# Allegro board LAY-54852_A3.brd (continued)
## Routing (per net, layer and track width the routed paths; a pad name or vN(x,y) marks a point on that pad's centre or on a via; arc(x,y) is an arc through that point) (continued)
GND_CHASSIS:
  vias: v1(78.14,8.1) v1(78.15,6) v1(78.44,1.46) v1(79.18,2.83) v1(80.35,1.39) v1(81.82,2.79) v1(83.01,1.44) v1(83.96,2.81) v1(84.07,12.31) v1(84.42,8.27) v1(84.43,6.17) v1(85.65,1.39) v1(85.84,12.38) v1(86.07,6.39) v1(86.08,4.3) v1(86.05,2.82) v1(86.61,10.86) v1(86.64,9.58) v1(87.42,12.33) v1(87.78,1.41) v1(87.83,5.11) v1(87.82,2.88) v1(88.38,10.93) v1(88.41,9.64) v1(88.85,12.37) v1(89.4,2.83) v1(89.53,8.55) v1(89.54,6.45) v1(89.88,1.42) v1(89.96,10.88) v1(89.99,9.59) v1(90.61,12.43) v1(91.6,1.38) v1(92.04,2.79) v1(92.2,12.38) v1(93.49,1.45) v1(94.18,2.81) v1(95.09,8.4) v1(95.06,6.62) v1(95.07,4.52) v1(95.83,1.57) v1(96.27,2.82) v1(97.18,8.41) v1(97.21,6.53) v1(97.22,4.44) v1(97.43,1.52)
VBUS1_DET_3V3: length 91.9
  TOP w0.081: U101.B3 85.25,56.45 85.25,56.98
  TOP w0.091: R301.1 22.87,29.43 22.06,30.24 22.06,36.23 23.34,37.51 27.24,37.51 29.46,39.73 32.2,39.73 32.77,40.31 32.77,44.52 34.72,46.47 45.94,46.47 45.96,46.45 v1(46.79,46.45) ; 85.25,56.98 85.25,57.34 84.83,57.76 84.83,60.33 84.46,60.7 82.98,60.7 82.25,61.43 69.75,61.43 65.64,57.31 56.67,57.31 55.44,56.08 55.44,51.03 54.06,49.65 51.51,49.65 47.7,45.84 v1(47.56,45.84)
  BOTTOM w0.091: v1(46.79,46.45) 46.98,46.25 47.15,46.25 v1(47.56,45.84)
VBUS_DBG: length 13.9
  TOP w0.381: J1708.A9 16.56,5.99 J1708.B4 ; J1708.B9 14.06,5.99 J1708.A4 14.06,7.84 TVS1401.2
  TOP w0.508: TVS1401.2 12.06,9.85 11.62,9.85 L1702.1
  BOTTOM w0.381: J1708.B9 14.11,7.65 14.81,8.35 16.04,8.35 16.51,7.87 J1708.B4
VBUS_IN:
  vias: v1(21.68,20.13) v1(21.68,19.52) v1(22.42,20.11) v1(22.43,19.47) v1(41.59,22.14) v1(41.6,21.53) v1(42.33,22.12) v1(42.35,21.48)
VBUS_OVLO_TH: length 3
  TOP w0.091: U302.B3 49.42,23.23 R304.2 49.71,23.51 R1759.1
VBUS_USB_DBG: length 7.4
  TOP w0.381: C1409.1 9.16,12.08 8.89,12.34 U1410.1 ; C1409.1 9.66,10.81 L1702.2 ; C1409.1 9.66,12.08 C1725.1 9.66,14.54 C1726.1 9.04,14.55 8.73,14.24 U1410.3
VCC_3V6: length 2.6
  TOP w0.305: U901.9 37.82,35.32 37.43,35.72 C907.1 36.69,36.56 R908.1
VCC_FT_1V8: length 38.9
  TOP w0.203: C1723.1 3.45,23.9 3.57,24.02 4.07,24.02 4.22,23.87 U1706.64
  TOP w0.254: v1(12.92,23.03) 13,22.95 U1706.12 ; v1(13.58,32.18) 13.53,32.18 13,32.71 U1706.37
  TOP w0.508: L1404.1 4.73,34.8 8.37,31.16 13.28,31.16 13.58,31.46 v1(13.58,32.18) ; v1(12.92,23.03) 12.15,23.8 7.39,23.8 6.74,23.16 C1723.1
  BOTTOM w0.508: C1724.1 v1(12.92,23.03) 12.92,24.05 13.58,24.71 v1(13.58,32.18) C1408.1
VCC_FT_3V3: length 247.7
  TOP w0.254: U1706.20 18.54,25.37 C1420.1 ; U1706.31 18.65,30.87 C1423.1 ; v1(4.36,30.73) 4.5,30.87 U1706.50 ; U1404.3 27.72,62.43 C1424.1 ; U1706.56 v1(4.27,27.87) ; v1(10.65,32.16) 10.5,32.31 U1706.42 ; U1713.2 11.77,48.51 12.95,47.33 C1720.1 ; U1409.21 20.96,53.72 C1461.1
  TOP w0.305: R1816.1 v1(10.38,58.21) ; R1815.1 v1(8.04,69.15)
  TOP w0.381: R1421.2 v1(9.74,39.66) ; R1452.1 v1(19.64,22.52) ; v1(20.12,29.66) 19.84,29.38 R1727.2 ; v1(135,45.74) R1053.1 135.08,45.06 R1056.1 ; v1(2.27,38.85) 2.62,39.2 R1735.1 ; R1453.1 5.51,58.72 v1(5.8,58.42) ; R1467.1 v1(7.09,65.4) ; R1730.2 7.51,39.02 v1(7.51,38.65) ; R1736.1 3.82,38.93 v1(3.9,38.85) ; U1406.8 14.56,60.79 C1432.1 v1(14.55,59.76) ; C1420.1 v1(18.58,25.95) ; R1468.1 5.59,61.48 v1(5.89,61.18) ; v1(18.4,53.59) 18.7,53.29 C1460.1 19.3,53.27 C1461.1 ; v1(12.71,65.05) 12.53,64.86 R1450.1 ; U1408.1 20.49,38.34 C1435.1 19.85,36.74 C1434.1 v1(19.98,35.98) ; C1720.1 13.51,47.3 C1719.1 v1(12.89,46.4) ; R1486.1 22.67,51.67 21.56,50.56 v1(18.61,50.56) ; D1703.C v1(15.29,15.91) ; C1423.1 18.68,31.13 v1(18.29,31.51) ; U1405.6 v1(4.67,40.81) ; v1(11.91,67.57) 11.88,67.54 C1433.1 12.38,66.82 12.53,66.97 U1407.6 ; R1485.1 16.3,54.8 v1(16.53,54.57) ; R1465.1 6.41,55.83 v1(6.46,55.78) ; C1424.1 27.27,61.98 C1425.1 27.27,60.35 26.92,60 25.75,60 25.32,60.43 25.32,64.14 R1451.1 24.54,65.34 24.2,65.68 23.32,65.68 22.57,66.42 20.25,66.42 17.57,63.74 v1(14.59,63.74) ; R1734.1 5.92,47.56 v1(5.71,47.77) ; R1742.1 v1(15.72,65.66) ; R1729.2 v1(13.16,40.12) ; L1703.1 v1(13.57,16.06) ; L1704.1 v1(8.23,16.12) ; v1(4.91,51.39) 5.15,51.63 R1733.2 ; R1748.1 v1(7.21,68.93) ; R1737.1 v1(16.55,18.14) ; R1726.2 v1(20.12,28.3)
  TOP w0.508: v1(2.61,14.6) 2.64,14.63 D1704.C
  BOTTOM w0.254: C1418.1 v1(4.36,30.73)
  BOTTOM w0.381: v1(4.27,27.87) 4.27,27.87 C1417.1 ; C1429.1 4.67,41.03 v1(4.67,40.81) ; v1(135,45.74) 133.81,46.93 133.81,69.57 133.92,69.68 133.92,77.39 126.42,84.89 14.94,84.89 13,82.95 13,81.09 13.19,80.9 13.19,69.8 11.91,68.51 v1(11.91,67.57) ; C1419.1 10.48,32.34 v1(10.65,32.16)
VDD_1V8: length 213.4
  TOP w0.127: v1(60.51,26.65) 61.07,26.65 61.66,27.25 U701.14
  TOP w0.203: v1(105.21,42.96) 105.21,43.02 104.98,43.24 U501.C6 ; U501.N4 U501.M4 ; U501.N4 U501.P3 103.29,37.71 v1(103.29,37.32) ; U501.N4 U501.P5 104.36,37.78 104.36,37.25 v1(104.36,37.25) ; v1(88.49,51.21) U101.L9 U101.L11 ; U101.L6 86.99,52.16 v1(86.95,52.2)
  TOP w0.254: C1436.1 20.84,40.11 21.26,39.69 U1408.11 ; R1779.1 96.13,30.73 v1(95.84,30.44) ; U201.T9 68.28,49.13 67.99,48.84 v1(67.96,48.84) ; C923.1 119.8,28.32 U906.1 ; v1(74.71,56.08) 74.71,55.68 U201.F1 ; v1(74.46,48.81) 74.46,48.87 U201.G9 ; v1(60.87,56.47) 61.14,56.74 66.57,56.74 v1(67.3,56.01) 67.63,55.68 U201.U1 ; U201.T4 68.28,53.28 v1(67.95,53.61) ; U201.G4 74.44,53.51 v1(74.44,53.62) ; U904.11 130.37,23.94 C1756.1
  TOP w0.305: v1(116.05,28.41) 116.05,23.26 115.04,22.26 115.04,20.91 R956.2
  TOP w0.381: v1(74.57,43.44) 79.55,43.44 80.06,42.94 80.06,39.41 77.38,36.73 77.38,34.74 v1(77.42,34.7) ; R952.1 v1(131.59,3.75) R951.1 ; v1(27.62,41.37) 27.27,41.03 R1460.1 26.89,40.86 26.16,40.12 v1(23.86,40.12) ; v1(15.28,79.12) 15.2,79.04 L1301.1 ; v1(61.02,58.83) 63.63,58.83 68,63.2 R1767.1 ; R502.1 97.51,39.12 v1(97.84,38.79) ; R501.1 v1(99.09,42.84) ; Q1406.2 28.58,54.01 R1756.1 v1(27.43,53.19) ; C1756.1 130.12,23.24 v1(129.68,23.24) ; C1437.1 19.85,39.98 C1436.1 19.98,41.47 D1407.A 21.78,43.27 23.79,43.27 v1(23.87,43.19) ; v1(97.34,67.77) 97.66,67.45 C802.1 99.67,67.37 U802.5 ; R510.1 v1(79.89,33.6) ; R1441.1 v1(47.87,66.67) ; R65.2 72.69,20.84 72.26,20.41 v1(72.17,20.41) 72.1,20.41 71.72,20.79 R64.2 ; v1(119.56,27.26) 119.3,27.53 C923.1 ; J1405.1 v1(49.71,69.7) ; v1(94.56,70.99) 92.88,70.99 92.41,71.46 90.25,71.46 89.67,72.05 v1(87.04,72.05) ; C1448.1 31.84,40.9 R1459.1 29.58,40.9 27.91,39.23 v1(27.62,39.23) ; v1(98.53,26.73) L1201.1 v1(99.19,26.01) ; v1(126.9,22.84) 126.9,20.87 127.36,20.41 v1(127.36,18.7)
  L2_GND w0.254: v1(88.49,51.21) 87.53,52.17 87.13,52.17 87.09,52.2 v1(86.95,52.2)
  L3_PWR w0.203: v1(74.44,53.62) 74.9,53.15 74.9,49.25 v1(74.46,48.81)
  BOTTOM w0.203: v1(60.51,26.65) 60.76,26.4 60.76,20.76 v1(59.43,19.43)
  BOTTOM w0.254: C201.1 67.28,56.03 v1(67.3,56.01) 68.53,54.78 C202.1 68.06,53.71 v1(67.95,53.61) ; v1(105.21,42.96) 105.14,43.03 C506.1 ; C504.1 104.36,36.51 v1(104.36,37.25) 104.37,37.25 C507.1 ; v1(88.49,51.21) 88.73,51.44 C116.1 ; v1(86.95,52.2) 86.98,52.17 C115.1 ; C505.1 103.14,37.47 v1(103.29,37.32) ; v1(74.71,56.08) 74.95,55.84 C203.1 74.95,54.91 74.44,54.39 v1(74.44,53.62) ; v1(67.96,48.84) 67.93,48.81 C209.1 67.93,47.03 v1(67.3,46.4) 67.37,46.34 C205.1
  BOTTOM w0.381: v1(94.56,70.99) 94.56,70.55 v1(97.34,67.77) ; v1(27.62,39.23) v1(27.62,41.37) 27.43,41.56 v1(27.43,53.19) 28.54,54.31 31.09,54.31 43.45,66.67 v1(47.87,66.67) ; v1(119.56,27.26) 119.47,27.36 C922.1 ; v1(92.15,76.92) 88.94,76.92 87.54,78.32 86.68,78.32 86.19,77.83 86.19,77.19 87.04,76.35 v1(87.04,72.05) ; v1(95.84,30.44) 95.84,32.66 99.39,36.2 ; v1(23.87,43.19) 24.18,42.88 24.18,40.45 v1(23.86,40.12)
  BOTTOM w0.508: v1(77.42,34.7) 77.47,34.65 78.84,34.65 v1(79.89,33.6)
  vias: v1(58.69,22.85) v1(58.7,22.27) v1(58.71,21.7) v1(59.16,73.59) v1(59.24,22.86) v1(59.26,22.27) v1(59.27,21.69) v1(59.56,73.19) v1(59.95,72.82) v1(60.78,47.25) v1(60.88,55.61) v1(60.85,46.35) v1(73.57,45.61) v1(74.62,46.35) v1(117.71,29.76) v1(117.84,28.54) v1(126.35,22.83) v1(126.59,23.28)
VDD_3V3: length 195.2
  TOP w0.127: U701.21 64.91,26.35
  TOP w0.203: U1709.G3 104.52,29.93 v1(104.7,30.11) ; U1709.A3 104.52,25.8 v1(104.49,25.77) ; U301.3 v1(68.24,15.3) ; U501.E6 v1(104.98,42.02) ; 65.52,26 65.38,26.14 65.38,26.51 65.31,26.58 U701.22 ; U101.H13 v1(90.49,52.73) U101.K13 ; U501.F5 104.21,41.9 104.17,41.94 v1(104.1,41.94) ; v1(65.63,22.46) 65.37,22.46 65.08,22.76 65.08,25.82 64.91,25.99 64.91,26.35 ; v1(88.47,54.71) U101.E8 ; U501.J10 107.22,40.4 v1(107.35,40.26) ; U501.K9 v1(106.48,39.45)
  TOP w0.254: C921.1 120.07,29.63 U906.11 ; U1713.3 12.23,48.91 12.48,49.16 C1722.1 ; C805.1 113.63,70.81 U805.14 ; C804.1 131.47,69.14 131.02,69.6 U803.14 ; C1401.1 122.52,69.22 121.71,68.41 U1401.8 ; C1703.1 25.17,74.27 U1702.14 ; C1755.1 130.51,25.29 U904.1 ; U1401.5 123.55,66.73 C1403.1 ; v1(37.36,15.25) 37.72,15.61 U401.3 ; R613.1 6.9,71.21 TP608.1 ; v1(106.21,62.42) 106.31,62.32 U801.27 ; C1426.1 27.6,62.83 U1404.2 ; R1502.1 v1(30.97,67.87) ; U804.14 v1(102.92,71.33)
  TOP w0.381: C1755.1 130.69,27.61 ; 130.69,27.61 v1(130.22,28.07) ; 130.69,27.61 133.4,27.61 R1813.1 ; v1(25.1,28.68) 24.78,29 R1768.1 ; v1(101.66,68.29) 101.36,68.29 101.33,68.33 R808.1 ; v1(117.82,61.37) 117.54,61.09 R817.1 ; C1703.1 C1704.1 v1(26.07,73.71) ; v1(27.83,64.15) 27.77,64.09 C1427.1 27.3,63.52 27.4,63.42 C1426.1 ; R1765.1 v1(66.58,9.72) ; D1703.A v1(18.78,16.66) ; R1420.1 v1(123.12,62.68) ; v1(85.15,38.34) 85.15,37.81 L501.1 84.27,37.8 v1(84.27,38.31) ; D1501.A 23.07,76.74 v1(23.09,76.73) ; v1(116.24,71.27) 116.42,71.09 R1402.1 R1404.1 ; C1201.1 104.75,30.6 104.7,30.55 v1(104.7,30.11) ; v1(123.56,70.14) C1401.1 123.58,69.2 C1404.1 123.62,67.78 C1403.1 v1(123.62,66.04) ; D1502.A 33.97,75.42 v1(34.11,75.28) ; U801.31 106.44,60.32 v1(106.34,60.22) ; R1403.1 116.12,65.3 v1(115.92,65.51) ; R309.1 v1(102.46,63.93) ; R705.1 v1(71.96,23.63) ; v1(95.15,25.07) 94.67,25.55 L502.1 95.4,27.25 95.4,28.35 95.05,28.7 R506.1 ; v1(12.76,48.2) C1721.1 C1722.1 ; R1407.1 94.55,73.43 v1(94.34,73.64) ; R804.1 v1(103.56,64.35) ; v1(13.06,52.45) 13.3,52.2 R1718.2 ; v1(113.81,72.58) C806.1 113.79,71.92 C805.1 ; R802.1 R801.1 v1(103.48,60.14) ; R306.1 R308.1 102.46,59.52 v1(102.41,59.57) ; J1406.2 61.98,73.53 C1412.1 v1(62.88,73.25) ; U1308.5 17.36,72.22 C1324.1 17.32,72.69 v1(17.15,72.86) ; R1221.1 113.79,35.67 113.79,35.73 v1(113.89,35.83) ; R1203.1 99.54,17.08 R1202.1 v1(100.25,16.32) ; v1(8.43,70.8) 8.01,71.21 TP608.1 ; R1762.1 v1(51.75,20.96) ; R604.1 v1(46.89,51.53) R603.1 v1(46.89,52.93) R602.1 v1(46.89,54.21) R601.1 ; v1(37.85,21.94) R431.1 36.99,21.41 R1775.1 ; R935.1 118.55,29.39 119.28,30.12 C921.1 119.64,30.78 v1(120.48,30.78) ; R1054.1 130.58,40.01 v1(130.43,39.86) ; R1827.1 v1(74.21,72.68) ; R923.1 v1(126.89,5.25) ; v1(127.82,31.92) 127.88,31.86 R950.1 ; R1333.1 v1(8.97,77.6) ; R505.1 v1(82.81,37.87) ; R913.2 v1(50.25,35.4) ; C804.1 C807.1 130.45,68.97 v1(130.13,69.3) ; v1(102.55,61.65) 102.46,61.73 R307.1 ; R1405.1 v1(122.48,73.69) ; U1307.5 16.83,77.05 C1325.1 16.79,77.53 v1(16.95,77.69) ; R1440.1 v1(47.87,68.92) ; R1406.1 v1(119.02,73.64) ; R213.1 v1(53.84,42.35) ; R1408.1 v1(92.04,73.64)
  TOP w0.762: J1406.1 J1406.2
  BOTTOM w0.203: C155.1 88.5,54.73 v1(88.47,54.71)
  BOTTOM w0.254: v1(90.56,61.26) 90.48,61.18 90.48,58.35 88.98,56.86 C155.1 ; U905.1 120.47,29.64 119.92,30.18 C920.1 ; C411.1 37.39,15.28 v1(37.36,15.25) ; C501.1 107.45,40.16 v1(107.35,40.26) ; U915.A1 116.37,77.71 C956.1 116.37,79.29 C955.1 ; C502.1 105,42 v1(104.98,42.02) ; v1(106.48,39.45) 106.51,39.42 C503.1 ; C119.1 92.03,52.75 C118.1 91.8,53.43 91.6,53.24 90.73,53.24 90.49,53 v1(90.49,52.73)
  BOTTOM w0.305: U908.11 114.43,24.98 C22.1 114.07,26.27 C1792.1 113.93,27.01 v1(113.69,27.25) ; R863.1 118.15,78.6 117.4,79.36 C955.1
  BOTTOM w0.381: v1(65.63,22.46) 66.79,23.63 v1(71.96,23.63) ; v1(120.48,30.78) 119.75,30.78 119.37,30.4 C920.1 ; v1(9.75,70.38) 8.92,69.55 8.92,66.19 10.49,64.62 10.49,60.43 13.06,57.86 v1(13.06,52.45) 13.06,48.5 v1(12.76,48.2) ; U1714.3 99.18,79.66 C1789.1 99.68,78.9 100.67,77.91 100.68,77.91 104.14,74.45 v1(104.51,74.45) ; R1080.1 46.85,52.98 v1(46.89,52.93) ; C955.1 116.44,80.04 116.71,80.31 119.24,80.31 120.82,78.72 v1(120.82,73.99) ; v1(68.24,15.3) 68.34,15.2 C307.1 ; v1(33.68,49.17) 34.08,48.77 R1081.1 35.48,48.8 R1076.1 R1075.1 ; v1(102.92,71.33) 103.2,71.62 C809.1 C808.1 ; C1231.1 103.72,26.66 C1202.1 103.93,26.33 v1(104.49,25.77) ; C801.1 106.34,62.29 v1(106.21,62.42)
  vias: v1(11.96,79.29) v1(12.47,79.27) v1(65.6,18.81) v1(65.6,19.38) v1(66.18,19.38) v1(66.18,18.85) v1(96.07,62.26)
VDD_5V: length 159.4
  TOP w0.254: U401.12 37.32,19.35 36.73,19.94 36.54,19.94 C413.2 ; v1(78.73,79.36) 79.05,79.36 D1402.2 79.15,80.22 v1(78.73,80.22) ; v1(40.4,75.27) 40.4,75.66 R1503.2 41.11,75.67 41.11,75.31 v1(41.03,75.23) ; U301.12 68.64,11.2 69.13,10.72 C309.2
  TOP w0.381: v1(69.59,11.36) 69.59,10.74 C309.2 ; v1(30.13,78.46) 30.43,78.16 R1501.2 ; TP904.1 53.83,37.25 53.41,37.67 52.2,37.67
  TOP w0.508: v1(111.89,18.34) 112.22,18.67 112.22,21.18 v1(112.42,21.39) ; C413.2 35.72,20.23 v1(35.72,19.93)
  TOP w0.635: U1202.3 113.14,30.12 v1(113.02,30.24)
  BOTTOM w0.508: C1219.1 113.29,28.97 111.55,27.23 111.55,22.26 v1(112.42,21.39) ; v1(35.72,19.93) 37.12,21.34 40.17,21.34 50.15,11.36 v1(69.59,11.36) 70.07,10.89 70.07,10.21 70.57,9.7 72.54,9.7 76.79,13.95 106.61,13.95 111,18.34 v1(111.89,18.34)
  BOTTOM w0.635: v1(113.02,30.24) 113.29,29.97 C1219.1
  BOTTOM w0.762: 25.01,35.37 25.01,36.91 25.99,37.9 25.99,55.81 25.16,56.64 25.16,58.55 26.91,60.29 26.91,74.27 30.94,78.3 30.96,78.3
  vias: v1(23.88,35.02) v1(24.39,35.03) v1(24.42,34.52) v1(32.48,79.26) v1(32.98,79.24) v1(33.49,79.22) v1(47.56,35.13) v1(47.56,34.57) v1(47.57,33.91) v1(48.04,34.23) v1(48.04,33.56)
VDD_ANA_0V8: length 7.1
  TOP w0.203: U101.F13 v1(90.49,53.73) ; U101.C4 v1(85.5,55.71) ; U101.M13 v1(90.49,51.69)
  TOP w0.381: v1(58.56,35.88) TP712.1 v1(58.54,36.71)
  L3_PWR w0.305: 90.72,53.33 90.49,53.55 v1(90.49,53.73)
  BOTTOM w0.203: C130.1 90.76,54.22 90.49,53.95 v1(90.49,53.73) ; v1(90.49,51.69) 90.49,52.15 C131.1
  BOTTOM w0.254: C132.1 v1(93.41,48.47) ; v1(85.5,55.71) 85.48,55.72 C133.1
  BOTTOM w0.381: v1(58.56,35.88) 59.15,35.29 R871.2
VDD_ANA_1V8: length 18.4
  TOP w0.203: v1(87.53,54.71) U101.E6 ; U101.F12 v1(89.52,54.21) ; U101.L12 v1(89.99,52.19)
  TOP w0.254: U101.N8 v1(87.49,50.71)
  TOP w0.508: v1(56.11,19.36) 55.9,19.57 L102.2 55.9,21.3 55.76,21.44
  TOP w0.635: 55.76,21.44 55.44,21.44 54.81,22.07 54.81,24.94 53.92,25.84 53.92,27.33 v1(54.47,27.89)
  L2_GND w0.254: v1(89.99,52.19) 89.9,52.19 88.99,51.28 88.99,51 88.7,50.71 v1(87.49,50.71)
  L3_PWR w0.152: 89.99,52.71 89.5,53.21 89.5,53.68
  L3_PWR w0.203: 89.99,52.71 v1(89.99,52.19)
  BOTTOM w0.203: C144.1 87.74,54.91 v1(87.53,54.71) ; C145.1 89.58,54.15 v1(89.52,54.21) ; C146.1 90.03,52.15 v1(89.99,52.19)
VDD_COIN_3V: length 9.8
  BOTTOM w0.381: R1082.1 37.03,58.17 38.44,59.58 39.14,59.58 39.68,59.04 39.68,58.37 40.07,57.98 BT1001.1 40.83,56.9 40.06,56.13 R1072.2
VDD_SNVS_0V8: length 1.6
  TOP w0.203: v1(89.49,55.71) U101.C10
  BOTTOM w0.254: v1(89.49,55.71) 89.49,56.23 89.49,56.24 89.49,56.76 C102.1
VDD_SOC_0V85: length 36.9
  TOP w0.203: v1(73.68,35.7) 73.06,35.08 R711.2 ; U101.K11 v1(89.49,52.71) U101.H11 ; U101.K7 v1(87.49,52.71) U101.H7
  TOP w0.254: TP703.1 73.21,34.47 R701.1
  L3_PWR w0.203: 90.11,49.53 90.55,49.09 90.55,41.72 84.27,35.44 73.93,35.44 v1(73.68,35.7)
  BOTTOM w0.203: v1(87.49,52.71) 87.46,52.74 C111.1 ; C104.1 88.86,52.83 v1(88.99,52.71) ; C107.1 89.48,52.72 v1(89.49,52.71) 89.51,52.68 C106.1
  BOTTOM w0.254: v1(87.49,52.71) 87.51,52.69 C110.1 ; v1(87.99,52.71) 87.99,52.27 C108.1 ; C109.1 86.51,42.59 C105.1 v1(86.98,42.58)
  vias: v1(75,36.72) v1(75.01,36.15) v1(75.69,36.7) v1(75.71,36.19) v1(76.42,36.64) v1(76.41,36.13)
VINT: length 1.8
  TOP w0.203: U701.4 60.92,31.95 v1(60.89,31.99)
  BOTTOM w0.381: C706.1 61.48,31.37 60.89,31.97 v1(60.89,31.99)
ADC_IN0: length 40.8
  TOP w0.081: 87.78,56.92 87.74,56.89 87.74,56.46 U101.B8
  TOP w0.091: 87.78,56.92 87.78,64.41 86.63,65.55 67.12,65.55 65.75,64.18 v1(65.75,63.94) ; v1(62.36,65.19) 61.82,65.73 TP408.1 61.79,67.91 C1413.1 60.68,67.9 R1442.2
  BOTTOM w0.091: v1(65.75,63.94) 64.49,65.19 v1(62.36,65.19)
ADC_IN1: length 39.1
  TOP w0.081: U101.A8 87.99,58.37
  TOP w0.091: R1444.2 60.75,64.54 C1414.1 60.79,64.49 TP409.1 61.97,64.81 v1(61.77,65.01) ; 87.99,58.37 87.99,64.5 86.72,65.77 67.03,65.77 65.18,63.92 65.18,63.79 v1(65.27,63.69)
  BOTTOM w0.091: v1(61.77,65.01) 62.2,64.58 64.39,64.58 v1(65.27,63.69)
ADCDAT1: length 2.7
  TOP w0.081: 106.05,28.07 105.27,28.07 U1709.D2
  TOP w0.102: 106.05,28.07 106.91,28.07 R1208.2
AUD_5V: length 8.4
  TOP w0.508: U1202.5 v1(111.24,30.89)
  TOP w0.635: v1(111.24,30.89) U1202.1
  BOTTOM w0.635: L1205.1 108.75,26.76 110.44,28.46 110.44,30.09 v1(111.24,30.89)
AUD_NINT: length 32.8
  TOP w0.091: R845.2 115.48,58.91 115.48,57.62 113.21,55.35 108.23,55.35 v1(108.14,55.44) ; R1221.2 112.67,35.34 R1204.1 112.67,37.36 113.2,37.88 v1(113.38,37.88)
  BOTTOM w0.091: v1(108.14,55.44) 108.14,55.34 108.17,55.31 108.17,52.01 112.9,47.28 112.9,38.37 v1(113.38,37.88)
AUD_PWREN: length 42.5
  TOP w0.091: R1219.1 112.23,34.73 112.23,37.32 v1(114.05,39.14) ; R831.2 111.82,68.43 108.95,68.43 108.76,68.24 v1(108.75,68.24)
  BOTTOM w0.091: v1(114.05,39.14) 114.08,39.17 114.08,41.05 113.85,41.28 113.85,47.72 111.12,50.46 111.12,53.2 110.8,53.52 110.8,56.19 111.32,56.71 111.32,65.3 108.67,67.95 108.67,68.15 v1(108.75,68.24)
AUD_SCL: length 4
  TOP w0.081: U1709.F1 106.44,28.82
  TOP w0.102: 106.44,28.82 106.55,28.93 106.55,30.66 R1212.2
AUD_SDA: length 3.9
  TOP w0.081: U1709.E2 105.27,28.58 105.76,28.58
  TOP w0.102: R1211.2 106.77,29.89 106.77,28.89 106.45,28.58 105.76,28.58
BCLK1: length 2.6
  TOP w0.081: 106.2,28.32 U1709.E1
  TOP w0.102: R1206.2 106.99,29.14 106.99,28.79 106.53,28.32 106.2,28.32
BT_MODE0: length 2.3
  TOP w0.091: R1731.2 29.5,59.99 U1404.6
BT_MODE1: length 2.1
  TOP w0.091: U1404.7 29.9,59.47 R1732.2
BT_MODE2: length 2.2
  TOP w0.091: R1418.2 30.3,59.77 U1404.8
BT_MODE3: length 3.5
  TOP w0.091: R1419.2 30.95,60.18 30.95,61.82 30.74,62.03 U1404.9
BUF_POR: length 4.3
  TOP w0.091: 101,66.44 101.06,66.51 R811.1 ; 101,66.44 U802.4 ; 101,66.44 R808.2
BYPASS1: length 2.3
  TOP w0.091: U401.4 38.12,15.37 C1737.2
CAN1_RX: length 13.5
  TOP w0.091: v1(22.2,73.03) 22.2,77.91 22.65,78.37 26.75,78.37 R1509.1 ; U1702.4 23.62,71.2 v1(23.56,71.14)
  BOTTOM w0.091: v1(22.2,73.03) 23.56,71.66 v1(23.56,71.14)
CAN1_TX: length 18.5
  TOP w0.091: U1702.1 22.12,72.4 21.82,72.7 21.82,77.85 22.56,78.59 27.58,78.59 28.03,79.03 30.36,79.03 R1508.1
CAN_H: length 18.4
  TOP w0.254: R1504.2 39.38,67.27 R1507.2 39.48,69.02 C1504.2 40.93,69.03 L1501.2 41.88,69.06 42.2,69.38 42.2,70.57 44.31,72.68 D1503.1 44.31,75.35 43.81,75.86 J1501.2
CAN_L: length 18.7
  TOP w0.254: J1501.3 46.19,80.08 D1503.2 46.19,73.98 42.62,70.4 42.62,69.41 42.96,69.06 L1501.3 43.64,68.89 C1509.1 45.08,68.77 R1510.2 45.14,66.86 R1511.1
CAN_RX: length 3.3
  TOP w0.254: R1505.2 R1509.2 27.72,76.65 U1501.4
CAN_STBY: length 82.1
  TOP w0.091: R837.2 103.66,67.18 101.89,68.95 93.37,68.95 91.95,70.37 89.67,70.37 89.36,70.69 70.37,70.69 69.93,70.25 61.26,70.25 57.72,73.78 49.92,73.78 v1(49.63,73.49) ; v1(41.71,73.43) 33.59,73.43 31.53,71.37 U1501.8 31.53,67.99 R1512.2
  BOTTOM w0.091: v1(41.71,73.43) 49.56,73.43 v1(49.63,73.49)
CAN_TX: length 3.2
  TOP w0.254: U1501.1 31.53,76.98 R1508.2 R1506.2
CAN_VDD_5V: length 4.3
  TOP w0.457: C1501.1 29.44,77.05 R1501.1
  TOP w0.508: U1501.3 28.99,75.85 28.36,76.47 C1502.1 C1501.1
CAN_VIO_3V3: length 8.3
  TOP w0.254: U1501.5 27.72,68 C1503.1
  TOP w0.381: R1502.2 30.41,67.12 R1512.1 v1(32.2,67.12) ; C1503.1 v1(28.41,67.99)
  BOTTOM w0.381: v1(28.41,67.99) 29.33,67.08 32.16,67.08 v1(32.2,67.12)
CANH: length 24
  TOP w0.254: U1501.7 30.26,69.05 29.59,68.38 29.59,67.01 29.97,66.63 33.11,66.63 38.67,61.07 41.53,61.07 42.04,61.59 42.04,63.99 L1501.1 39.61,66.42 R1507.1
CANL: length 25.1
  TOP w0.254: R1510.1 43.98,65.06 L1501.4 42.46,64.06 42.46,61.47 41.68,60.69 38.51,60.69 32.99,66.21 29.78,66.21 28.99,67.01 U1501.6
CLKIN1: length 9.9
  TOP w0.081: U101.A6 86.99,56.85 87.07,56.93 87.07,58.37
  TOP w0.091: 87.07,58.37 87.07,61.94 85.89,63.12 TP411.1 85.45,63.46 83.32,63.46 R415.1
CLKIN2: length 10.2
  TOP w0.081: 86.74,56.88 86.74,56.46 U101.B6
  TOP w0.091: 86.74,56.88 86.86,57 86.86,61.85 86.01,62.7 84.97,62.7 TP412.1 84.6,63.01 83.67,63.01 R423.1
CLKOUT2: length 4.4
  TOP w0.081: 103.63,30.71 103.63,30.49 103.45,30.31 103.45,29.86 103.77,29.54 103.77,28.57 U1709.E4
  TOP w0.091: TP1948.1 103.63,31.7 103.63,30.71
CLKOUT5: length 2
  TOP w0.081: U1709.G6 103.02,29.44 102.71,29.76 102.71,30.36 103.05,30.71
  TOP w0.091: TP1950.1 103.05,30.71
CON_JTAG_NRST: length 10.6
  TOP w0.091: D1409.C 23.44,47.33 D1408.C 23.51,46.11 23.84,45.78 25.31,45.78 25.67,45.41 J1704.10 25.67,41.99 R1461.2
CPCA: length 6.7
  TOP w0.076: 102.77,26.57 U1709.B6
  TOP w0.081: 102.77,26.57 102.32,26.57 102.06,26.31
  TOP w0.152: 102.06,26.31 102.06,25.95 100.81,24.69 100.27,24.69 100.01,24.43 100.01,22.94 99.54,22.47 C1761.1
CPCB: length 4.9
  TOP w0.076: U1709.B7 102.27,26.82 101.97,26.53
  TOP w0.102: 101.73,26.28 101.97,26.53
  TOP w0.152: 101.73,26.28 100.68,25.23 99.8,25.23 99.2,24.63 C1761.2
CPVOUTN: length 3
  TOP w0.152: C1762.1 100.86,24.22 102.52,25.88 U1709.A7
CPVOUTP: length 2.6
  TOP w0.152: C1763.1 102.92,24.52 102.92,26.22 U1709.A6
DACDAT1: length 2
  TOP w0.081: 106.23,27.82 U1709.D1
  TOP w0.102: R1207.2 107.16,27.82 106.23,27.82
DBG_ACC: length 2.3
  TOP w0.091: TP1926.1 38.52,20.55 U401.9
DMIC_PDM_CLK: length 8.4
  TOP w0.091: U1702.16 23.75,73 22.71,74.05 v1(22.71,75.93) ; U1309.2 20.16,77.55 v1(20.19,77.52)
  BOTTOM w0.091: v1(20.19,77.52) 21.78,75.93 v1(22.71,75.93)
DMIC_PDM_DATA0: length 9.9
  TOP w0.091: U1702.3 23.42,71.6 22.75,70.93 21.62,70.93 20.55,71.99 20.55,75.12 19.42,76.26 U1307.4
DMIC_PDM_DATA1: length 8.1
  TOP w0.091: U1308.4 19.95,71.9 21.41,70.45 v1(23.76,70.45) ; U1702.9 25.94,71.2 26.12,71.02 v1(26.12,70.45)
  BOTTOM w0.091: v1(26.12,70.45) v1(23.76,70.45)
DRAM_CA0_A: length 23.1
  TOP w0.089: 76.93,57.13 77.02,57.04 TP219.1 77.2,57.04 77.29,57.13
  TOP w0.091: 76.93,57.13 76.93,57.57 76.83,57.66 76.65,57.66 76.56,57.57 76.56,57.07 76.44,56.95 76.31,56.95 76.19,57.07 76.19,57.57 76.1,57.66 75.92,57.66 75.83,57.57 75.83,57.07 75.74,56.98 75.55,56.98 75.46,57.07 75.46,57.57 75.37,57.66 75.24,57.66 75.15,57.57 75.15,56.66 75.02,56.52 73.9,56.52 73.81,56.43 73.81,55.5 73.63,55.33 73.63,55.2 73.81,55.02 73.81,54.84 73.71,54.75 73.53,54.75 U201.H2 ; U101.F1 84.41,54.12 84.17,54.12 84,54.29 83.85,54.29 83.79,54.35 83.79,54.49 83.71,54.57 83.53,54.57 83.46,54.5 83.46,54.33 83.4,54.28 83.2,54.28 83.14,54.34 83.14,54.46 83.02,54.57 82.33,54.57 82.12,54.78 81.99,54.78 81.89,54.68 81.7,54.68 81.6,54.77 81.6,55.03 81.52,55.11 81.39,55.11 81.3,55.2 81.3,55.52 81.2,55.62 81.03,55.62 80.77,55.35 80.77,55.22 81.24,54.75 81.24,54.62 81.11,54.5 80.98,54.5 78.39,57.09 78.39,57.57 78.3,57.66 78.11,57.66 78.02,57.57 78.02,57.04 77.93,56.95 77.78,56.95 77.66,57.07 77.66,57.57 77.57,57.66 77.38,57.66 77.29,57.57 77.29,57.13
DRAM_CA1_A: length 21.1
  TOP w0.081: U101.E2 84.99,54.83 84.87,54.95 84.39,54.95
  TOP w0.091: U201.J2 72.58,54.81 72.48,54.9 72.48,56.2 72.39,56.29 71.87,56.29 71.81,56.36 71.81,56.52 71.9,56.61 72.57,56.61 72.69,56.73 72.69,56.94 73.58,57.83 73.71,57.83 73.78,57.75 73.78,57.66 72.99,56.87 72.99,56.74 73.06,56.67 73.19,56.67 74.07,57.56 74.48,57.56 74.55,57.62 74.55,58.13 74.64,58.22 79.3,58.22 82.57,54.95 84.39,54.95
DRAM_CA2_A: length 34.1
  TOP w0.076: U101.D2 85.03,55.24 85.03,55.35 84.92,55.46 84.27,55.46
  TOP w0.091: 84.27,55.46 84.07,55.46 83.85,55.68 83.61,55.68 83.52,55.77 83.52,55.99 83.42,56.09 83.26,56.09 83.09,56.25 83.09,56.44 82.93,56.6 82.74,56.6 82.57,56.77 82.57,56.96 82.38,57.15 81.12,57.15 79.29,58.97 73.5,58.97 73.13,58.6 73.13,58.47 73.26,58.35 73.26,58.22 73.13,58.09 73,58.09 72.87,58.22 72.74,58.22 72.61,58.09 72.61,57.96 72.74,57.83 72.74,57.7 72.61,57.57 72.48,57.57 72.37,57.69 72.24,57.69 72.11,57.56 72.11,57.43 72.22,57.31 72.22,57.18 72.09,57.05 71.96,57.05 71.85,57.17 71.72,57.17 71.29,56.74 71.29,53.82 71.59,53.52 71.59,53.39 71.3,53.1 71.3,52.8 71.59,52.5 71.59,52.37 71.48,52.25 71.36,52.25 71.29,52.18 71.29,51.75 71.38,51.66 71.56,51.66 71.64,51.58 71.64,51.4 71.77,51.27 71.94,51.27 72.08,51.41 72.08,51.68 72.18,51.79 72.32,51.79 72.41,51.7 72.41,51.38 72.52,51.27 72.72,51.27 72.85,51.4 72.85,52.02 72.97,52.13 73.12,52.13 73.27,51.99 73.27,51.79 73.36,51.69 73.54,51.69 73.64,51.8 73.64,52.06 73.73,52.15 73.97,52.15 74.09,52.03 74.09,51.8 74.2,51.69 74.76,51.69 75.15,51.31 75.15,51.18 74.81,50.84 73.99,50.84 73.9,50.75 73.9,50.21 73.82,50.13 73.82,49.87 73.66,49.71 73.66,49.61 73.82,49.45 73.82,49.25 73.73,49.16 73.53,49.16 U201.H9
DRAM_CA3_A: length 32.9
  TOP w0.091: U201.H10 73.48,48.43 73.61,48.56 73.74,48.56 73.83,48.65 73.83,48.78 73.74,48.88 73.23,48.88 73.13,48.97 73.13,49.35 73.28,49.5 73.28,49.77 73.13,49.92 73.13,50.13 72.87,50.39 72.87,50.88 73.05,51.06 73.18,51.06 73.45,50.79 73.58,50.79 73.87,51.08 74.6,51.08 74.69,51.17 74.69,51.39 74.6,51.48 73.2,51.48 72.81,51.09 71.66,51.09 71.08,51.67 71.08,56.87 71.25,57.04 71.25,57.17 71.1,57.32 71.1,57.45 71.23,57.57 71.36,57.57 71.53,57.41 71.59,57.41 71.73,57.54 71.73,57.67 71.65,57.75 71.65,57.88 71.78,58.01 71.91,58.01 71.99,57.93 72.11,57.93 72.24,58.06 72.24,58.18 72.14,58.28 72.14,58.41 72.27,58.54 72.4,58.54 72.5,58.44 72.63,58.44 72.76,58.57 72.76,58.7 72.66,58.8 72.66,58.93 72.79,59.06 72.92,59.06 73.02,58.96 73.15,58.96 73.41,59.22 79.43,59.22 81.26,57.39 82.53,57.39 83.73,56.19 83.73,56.01 83.82,55.92 84,55.92 84.21,55.71 U101.C1
DRAM_CA4_A: length 33
  TOP w0.076: 84.74,56.31 84.74,56.9
  TOP w0.081: U101.B2 84.85,56.21 84.74,56.31
  TOP w0.091: 84.74,56.9 84.63,57.02 84.63,57.18 83.01,58.8 83.01,59.49 82.34,60.17 72.76,60.17 69.26,56.66 69.26,52.3 69.64,51.91 69.64,51.79 69.53,51.67 69.53,51.54 69.66,51.41 69.79,51.41 69.9,51.53 70.03,51.53 70.16,51.4 70.16,51.27 70.05,51.15 70.05,51.02 70.17,50.9 70.3,50.9 70.42,51.01 70.55,51.01 70.68,50.88 70.68,50.75 70.56,50.64 70.56,50.51 70.69,50.38 70.82,50.38 70.94,50.49 71.06,50.49 71.22,50.34 71.22,48.8 71.31,48.71 73,48.71 73.14,48.57 73.14,47.7 73.23,47.61 U201.H11
DRAM_CA5_A: length 31.7
  TOP w0.091: U101.A2 84.99,57.01 84.84,57.16 84.84,57.35 83.27,58.92 83.27,59.58 82.44,60.41 72.66,60.41 68.61,56.35 68.61,52.03 69.77,50.86 69.8,50.86 70.97,49.7 70.97,48.36 72.02,47.3 72.53,47.3 U201.J11
DRAM_CK_C_A: length 26.8
  TOP w0.094: U201.J9 72.83,49.32 v1(72.51,49.64) 72.11,49.64 71.88,49.88 71.88,50.22 70.54,51.56 70.54,57.52 72.8,59.78 79.61,59.78 81.48,57.91 82.72,57.91 84.43,56.21 U101.B1
  BOTTOM w0.094: v1(72.51,49.64) 72.6,49.64 73.13,49.11 R205.2
DRAM_CK_T_A: length 26.9
  TOP w0.076: 84.31,56 84.36,55.95 84.96,55.95 85.04,55.87 85.04,55.75 U101.C2
  TOP w0.091: 72.39,50.82 72.49,50.72 v1(72.49,50.38)
  TOP w0.094: v1(72.49,50.38) 72.49,50.1 72.58,50.01 U201.J8 ; 72.39,50.82 72.21,50.82 72.12,50.73 71.66,50.73 70.74,51.64 70.74,57.43 72.88,59.57 79.53,59.57 81.4,57.71 82.6,57.71 84.31,56
  BOTTOM w0.094: R205.1 72.7,50.38 v1(72.49,50.38)
DRAM_CKE0_A: length 18.6
  TOP w0.091: U101.G1 84.42,53.78 83.9,53.78 83.75,53.92 81.91,53.92 81.5,54.33 v1(81.5,54.37)
  TOP w0.104: v1(72.53,52.87) 72.55,52.89 72.55,52.92 U201.J4
  BOTTOM w0.091: v1(81.5,54.37) 81.5,55.04 79.29,57.25 73.15,57.25 72.44,56.53 72.44,55.74 72.83,55.35 72.83,54.16 72.71,54.03 R207.2 72.71,53.05 v1(72.53,52.87)
DRAM_CKE1_A: length 19.3
  TOP w0.076: U101.F2 84.74,53.95 84.02,53.95
  TOP w0.091: v1(82.75,54.25) 82.89,54.11 83.86,54.11 84.02,53.95
  TOP w0.104: U201.J5 72.53,52.1 v1(72.53,52.07)
  BOTTOM w0.081: 80.97,54.28 81.38,53.87 82.38,53.87 v1(82.75,54.25) ; 73.46,56.81 73.16,56.51 73.16,54.12 73.21,54.07 73.21,52.39 R208.2 72.66,52.2 v1(72.53,52.07) ; 78.74,56.81 78.74,56.8
  BOTTOM w0.089: 78.74,56.81 78.59,56.96 73.61,56.96 73.52,56.87 73.52,56.87 73.46,56.81 ; 78.74,56.8 79.57,55.98 79.57,55.69 80.97,54.28
DRAM_DATA0_A: length 12.5
  TOP w0.076: 84.31,51.46 84.75,51.46 U101.L2
  TOP w0.091: U201.F4 75.09,52.89 75.09,51.61 75.36,51.34 79.13,51.34 TP206.1 80.85,51.44 81.54,50.75 82.16,50.75 82.87,51.45 84.31,51.45 84.31,51.46
DRAM_DATA1_A: length 10.6
  TOP w0.091: U101.L1 83.12,51.71 82.73,52.1 81.62,52.1 81.51,51.98 TP207.1 79.59,52.08 78.4,52.08 77.98,51.66 76.1,51.66 75.76,52 75.76,52.87 U201.E4
DRAM_DATA2_A: length 8.9
  TOP w0.076: U101.K2 84.75,51.96 84.23,51.96
  TOP w0.091: 84.23,51.96 83.41,51.96 83.06,52.3 79.91,52.3 79.73,52.48 TP208.1 78.85,52.79 77.14,52.79 U201.C4
DRAM_DATA3_A: length 8
  TOP w0.091: U101.K1 83.4,52.21 83.06,52.54 80.15,52.54 79.69,53.01 TP209.1 79.18,53.01 78.58,53.61 77.47,53.61 77.38,53.52 U201.B4
DRAM_DATA4_A: length 8.3
  TOP w0.091: U201.B2 77.79,55.21 78.22,55.21 79.16,54.27 TP202.1 79.45,54.08 79.63,54.08 80.68,53.03 83.12,53.03 83.45,52.71 U101.J1
DRAM_DATA5_A: length 10.6
  TOP w0.076: 84.25,52.96 84.74,52.96 U101.H2
  TOP w0.091: 84.25,52.96 83.57,52.96 83.25,53.28 80.79,53.28 79.22,54.84 TP203.1 79.11,54.84 78.55,55.4 78.55,55.6 78.18,55.97 77.19,55.97 77.05,55.83 77.05,55.12 U201.C2
DRAM_DATA6_A: length 11.5
  TOP w0.091: U201.E2 75.74,55.12 75.74,55.89 76.18,56.32 78.25,56.32 TP204.1 79.11,55.41 79.59,54.92 79.59,54.86 80.93,53.52 83.39,53.52 83.71,53.21 U101.H1
DRAM_DATA7_A: length 13.2
  TOP w0.076: 83.76,53.46 84.75,53.46 U101.G2
  TOP w0.091: 83.76,53.46 83.48,53.74 81.54,53.74 81.39,53.89 81.08,53.89 TP205.1 79.64,55.33 79.64,55.45 78.47,56.61 75.35,56.61 75.09,56.36 75.09,55.12 U201.F2
DRAM_DATA8_A: length 12
  TOP w0.076: 84.27,48.96 84.74,48.96 U101.T2
  TOP w0.091: 84.27,48.96 82.76,47.44 81.01,47.44 79.53,45.96 TP212.1 76.3,45.96 75.74,46.52 75.74,47.29 U201.E11
DRAM_DATA9_A: length 13.8
  TOP w0.091: U201.F11 75.09,47.29 75.09,46.17 75.74,45.53 TP213.1 80.51,45.24 82.34,45.24 83.12,46.02 83.12,46.45 84.99,48.33 U101.U2
DRAM_DATA10_A: length 9.8
  TOP w0.091: U201.C11 77.05,47.29 77.05,46.58 77.19,46.43 79.37,46.43 TP211.1 80.67,47.74 82.63,47.74 84.1,49.21 U101.T1
DRAM_DATA11_A: length 8.8
  TOP w0.076: U101.R2 84.74,49.46 83.92,49.46
  TOP w0.091: 83.92,49.46 82.51,48.04 79.96,48.04 TP210.1 79.11,47.2 77.79,47.2 U201.B11
DRAM_DATA12_A: length 8.4
  TOP w0.091: U101.N1 84.19,50.71 84.14,50.65 83.13,50.65 82.38,49.89 79.86,49.89 TP216.1 79.58,49.62 77.14,49.62 U201.C9
DRAM_DATA13_A: length 8.6
  TOP w0.076: U101.N2 84.74,50.45 84.25,50.45
  TOP w0.091: U201.B9 77.78,48.81 78.91,48.81 TP217.1 79.22,49.11 81.01,49.11 81.41,49.51 82.31,49.51 83.21,50.41 84.2,50.41 84.25,50.45
DRAM_DATA14_A: length 11.4
  TOP w0.076: U101.M2 84.74,50.95 84.24,50.95
  TOP w0.091: 84.24,50.95 83.91,50.95 83.87,50.91 83.01,50.91 82.29,50.19 79.35,50.19 TP215.1 79.12,50.32 78.69,50.75 76.1,50.75 75.76,50.41 75.76,49.54 U201.E9
DRAM_DATA15_A: length 11.7
  TOP w0.089: TP214.1 80.25,50.49 81.37,50.49
  TOP w0.091: 81.37,50.49 82.19,50.49 82.91,51.21 U101.M1 ; U201.F9 75.09,49.52 75.09,50.8 75.32,51.02 78.9,51.02 78.91,51.02 TP214.1
DRAM_DMI0_A: length 9.4
  TOP w0.076: 84.11,52.45 84.74,52.45 U101.J2
  TOP w0.091: 84.11,52.45 84.1,52.47 83.39,52.47 83.06,52.79 80.44,52.79 79.65,53.58 TP201.1 78.9,54.02 78.9,54.07 78.57,54.4 77.13,54.4 U201.C3
DRAM_DMI1_A: length 8.6
  TOP w0.091: U201.C10 77.13,48.01 78.98,48.01 79.31,48.34 82.38,48.34 83.75,49.71 U101.R1
DRAM_NCS0_A: length 27
  TOP w0.091: U101.D1 83.99,55.21 83.75,55.44 83.58,55.44 83.35,55.21 82.77,55.21 81.79,56.18 81.79,56.32 81.91,56.44 82.09,56.44 83.04,55.49 83.19,55.49 83.28,55.58 83.28,55.7 82.23,56.76 81.89,56.76 81.68,56.54 81.33,56.54 79.19,58.67 79.06,58.67 78.91,58.52 78.78,58.52 78.61,58.69 78.38,58.69 78.29,58.59 78.29,58.56 78.2,58.47 78.01,58.47 77.92,58.56 77.92,58.59 77.83,58.69 77.65,58.69 77.56,58.59 77.56,58.56 77.47,58.47 77.28,58.47 77.19,58.56 77.19,58.59 77.1,58.69 76.92,58.69 76.83,58.59 76.83,58.56 76.73,58.47 76.55,58.47 76.46,58.56 76.46,58.59 76.37,58.69 76.19,58.69 76.09,58.59 76.09,58.56 76,58.47 75.82,58.47 75.73,58.56 75.73,58.59 75.64,58.69 75.45,58.69 75.36,58.59 75.36,58.56 75.27,58.47 75.09,58.47 75,58.56 75,58.59 74.91,58.69 74.72,58.69 74.63,58.59 74.63,58.56 74.54,58.47 74.36,58.47 74.27,58.56 74.27,58.59 74.17,58.69 73.89,58.69 73.77,58.57 73.77,58.36 TP218.1 73.67,58.29 72.45,57.07 72.45,56.98 72.28,56.81 71.71,56.81 71.46,56.56 71.46,54.01 71.92,53.55 72.95,53.55 73.13,53.36 73.13,52.92 73.26,52.79 73.39,52.79 73.44,52.83 73.44,53.16 U201.H4
DRAM_NCS1_A: length 27.7
  TOP w0.091: U201.H3 73.48,54.08 73.57,54.17 73.79,54.17 73.89,54.27 73.89,54.41 73.8,54.5 73.48,54.5 73.23,54.25 73.06,54.25 72.96,54.34 72.96,54.51 73.15,54.7 73.15,54.99 72.97,55.17 72.97,55.3 73.15,55.48 73.15,56.29 73.58,56.72 73.81,56.72 73.9,56.81 73.9,57.04 74.17,57.31 74.41,57.31 74.5,57.22 74.5,57.12 74.41,57.02 74.25,57.02 74.22,56.99 74.22,56.85 74.31,56.76 74.82,56.76 74.91,56.84 74.91,57.15 74.79,57.27 74.79,57.4 74.91,57.51 74.91,57.67 74.82,57.76 74.82,57.89 74.91,57.98 75.4,57.98 75.55,57.83 75.71,57.83 75.87,57.98 76.22,57.98 76.35,57.85 76.46,57.85 76.58,57.98 76.86,57.98 77,57.84 77.19,57.84 77.33,57.98 77.63,57.98 77.74,57.87 77.75,57.86 77.98,57.86 78.1,57.98 78.86,57.98 78.95,57.89 78.95,57.76 78.84,57.64 78.7,57.64 78.63,57.58 78.63,57.24 78.68,57.2 78.81,57.2 79.26,57.65 79.38,57.65 79.48,57.56 79.48,57.49 79,57.01 79,56.88 79.05,56.83 79.21,56.83 79.67,57.29 79.8,57.29 79.89,57.2 79.89,57.07 79.45,56.63 79.45,56.5 79.56,56.4 79.69,56.4 80.12,56.84 80.25,56.84 80.34,56.74 80.34,56.61 79.84,56.11 79.84,55.98 79.93,55.89 80.06,55.89 80.58,56.41 80.71,56.41 80.8,56.32 80.8,56.19 80.31,55.7 80.31,55.57 80.4,55.48 80.53,55.48 81.05,56 81.18,56 82.42,54.76 83.93,54.76 84.02,54.67 84.02,54.52 84.12,54.43 84.38,54.43 84.51,54.56 84.51,54.69 U101.E1
DRAM_NRESET: length 41.1
  TOP w0.081: v1(85.99,54.7) 85.99,54.7 U101.F4
  TOP w0.091: U201.T11 68.66,47.99 69.07,47.99 69.23,48.15 69.23,50.23 68.56,50.91 67.85,50.91 66.65,52.1 66.65,54.93 66.97,55.25 67.79,55.25 67.94,55.4 67.94,56.39 72.42,60.87 82.41,60.87 83.9,59.38 v1(83.9,58.9)
  TOP w0.112: U201.T11 68.28,47.53 v1(68.6,47.22)
  BOTTOM w0.081: R102.1 71.81,46.77 71.54,46.77 71.43,46.65 70.4,46.65 70.27,46.78 69.6,46.78 69.19,47.19 R201.1 68.66,47.28 v1(68.6,47.22)
  BOTTOM w0.091: v1(85.99,54.7) 85.89,54.8 85.89,56.85 83.9,58.84 v1(83.9,58.9)
DRAM_SDQS0_C_A: length 13.1
  TOP w0.094: U201.E3 75.43,53.92 75.75,53.6 v1(75.8,53.6) ; v1(85.99,52.7) 85.81,52.52 85.81,52.39 U101.K4
  BOTTOM w0.094: v1(75.8,53.6) 75.88,53.69 75.88,54.12 76.3,54.54 79.4,54.54 81.57,52.37 85.66,52.37 v1(85.99,52.7)
DRAM_SDQS0_T_A: length 12.9
  TOP w0.094: U101.M4 v1(85.99,51.7) ; v1(76.35,53.66) 76.23,53.66 76.08,53.81 U201.D3
  BOTTOM w0.094: v1(85.99,51.7) 85.99,52.01 85.84,52.17 81.48,52.17 79.32,54.33 76.38,54.33 76.08,54.03 76.08,53.76 76.18,53.66 v1(76.35,53.66)
DRAM_SDQS1_C_A: length 11.5
  TOP w0.076: U101.P2 84.74,49.95 83.95,49.95 83.93,49.93
  TOP w0.094: 83.93,49.93 83.86,49.93 83.84,49.96 83.52,49.96 82.26,48.7 v1(82.26,48.69) ; v1(75.77,48.79) 75.77,48.75 U201.E10
  BOTTOM w0.094: v1(82.26,48.69) 82.09,48.69 81.05,47.65 76.63,47.65 75.9,48.39 75.9,48.67 v1(75.77,48.79)
DRAM_SDQS1_T_A: length 11.3
  TOP w0.076: U101.P1 83.88,50.21
  TOP w0.094: U201.D10 76.08,48.68 76.21,48.81 v1(76.45,48.81) ; v1(81.72,49.01) 82.28,49.01 83.43,50.16 83.84,50.16 83.88,50.21
  BOTTOM w0.094: v1(76.45,48.81) 76.19,48.79 76.1,48.7 76.11,48.47 76.72,47.86 80.97,47.86 81.86,48.75 81.86,48.88 v1(81.72,49.01)
DRAM_ZN: length 3.2
  TOP w0.081: U101.H4 v1(85.99,53.7)
  BOTTOM w0.081: R204.1 84.09,53.06 85.3,53.06 85.95,53.7 v1(85.99,53.7)
DRAM_ZQ0: length 1
  TOP w0.254: U201.A5 v1(78.5,52.41)
  BOTTOM w0.081: v1(78.5,52.41) 78.13,52.78 R209.2
EMMC_VDDIM: length 2.2
  TOP w0.076: U501.C2 102.74,43.15 v1(102.05,43.15)
  BOTTOM w0.254: v1(102.05,43.15) 102.03,43.13 C508.1 101.53,43.13 C509.1
EN_SNK: length 3
  TOP w0.091: U402.F1 28.77,17.75 29.25,18.23 R411.2
EN_SRC: length 3.3
  TOP w0.091: R410.2 30,19.34 28.82,18.15 U402.G1
ENET1_MDC: length 26
  TOP w0.081: 87.75,48.45 87.75,48.96 U101.T8
  TOP w0.091: v1(94.77,30.34) 94.54,30.34 R503.1 ; v1(95.28,33.2) 96.29,33.2 97.86,34.77 97.86,35.98 87.75,46.1 87.75,48.45
  BOTTOM w0.091: v1(94.77,30.34) 95.28,30.85 v1(95.28,33.2)
ENET1_MDIO: length 25.2
  TOP w0.091: R1780.1 v1(94.73,30.99) R1779.2 ; U101.U7 87.49,46.04 97.64,35.89 97.64,34.86 96.36,33.58 95.12,33.58 94.75,33.21 v1(94.75,33.21)
  BOTTOM w0.091: v1(94.75,33.21) 94.74,33.2 94.74,31 v1(94.73,30.99)
ENET1_NINT: length 103.7
  TOP w0.091: U1712.31 86.31,33.24 84.1,35.46 84.1,36.78 R505.2 83.56,37.22 83,36.66 80.32,36.66 79.62,35.96 79.62,34.18 78.81,33.36 78.81,24.92 78.48,24.59 78.48,23.88 78.39,23.79 v1(78.39,23.79) ; v1(102.22,72.83) 102.1,72.71 U804.16
  BOTTOM w0.091: v1(78.39,23.79) 78.54,23.79 78.7,23.95 92.21,23.95 101.79,33.53 102.75,33.53 103.38,34.16 109.64,34.16 112.24,36.76 112.24,46.96 101.21,57.99 101.21,71.62 102.22,72.63 v1(102.22,72.83)
ENET1_NRST: length 74
  TOP w0.091: R826.2 115.42,65.25 v1(115.97,64.69) ; 93.3,28.73 93.3,29.06 93.52,29.28 95.19,29.28 95.81,28.66 v1(95.81,25.69) ; 93.3,28.73 92.21,29.82 U1712.12 ; 93.3,28.73 R506.2
  BOTTOM w0.091: v1(95.81,25.69) 95.81,25.95 101.71,31.85 109.65,31.85 110.75,32.94 120.36,32.94 121.55,34.13 121.55,35.78 119.63,37.71 119.63,42.01 117.96,43.68 117.96,48.79 114.7,52.04 114.7,56.37 116.84,58.51 116.84,64.17 116.32,64.69 v1(115.97,64.69)
ENET1_RD0: length 17.3
  TOP w0.091: U1712.25 88.97,35.06 R526.1 89.45,36.55 89.45,38.25 R517.2 89.92,38.85 89,39.76 89,42.27 86.53,44.75 86.53,48.67 U101.U5
ENET1_RD1: length 18.5
  TOP w0.081: U101.T6 86.74,48.96 86.74,48.22
  TOP w0.091: 86.74,48.22 86.74,44.89 90.42,41.21 90.42,39.22 R518.2 90.48,38.26 90.48,36.53 R527.1 90.24,35.31 90.09,35.31 89.37,34.59 U1712.24
ENET1_RD2: length 18.7
  TOP w0.091: U1712.23 89.77,34.38 90.3,34.9 90.85,34.9 R522.1 91.47,36.56 91.47,38.23 R514.2 91.95,38.87 91.42,39.4 91.42,40.89 86.99,45.31 U101.U6
ENET1_RD3: length 20.2
  TOP w0.081: 87.24,48.32 87.24,48.96 U101.T7
  TOP w0.091: 87.24,48.32 87.24,45.87 92.47,40.64 92.47,39.23 92.64,39.06 92.64,39.04 R515.2 92.5,38.25 92.5,36.55 R523.1 91.48,34.52 90.48,34.52 90.17,34.22 U1712.22
ENET1_RX_CTL: length 17.2
  TOP w0.081: U101.T5 86.24,48.95 86.24,48.42
  TOP w0.091: 86.24,48.42 86.24,44.72 88.77,42.19 88.77,38.65 88.45,38.33 88.45,36.53 R525.1 88.57,35.67 U1712.26
ENET1_RXC: length 18.5
  TOP w0.081: 86.03,48.67 U101.U4
  TOP w0.091: 86.03,48.67 86.03,44.48 88.52,41.99 88.52,38.93 88.43,38.84 R516.2 87.88,38.84 C519.1 86.74,37.99 87.4,37.33 87.4,36.57 R524.1 87.93,35.16 88.32,34.77 88.32,34.27 88.17,34.12 U1712.27
ENET1_TD0: length 26.7
  TOP w0.091: U101.U9 88.46,48.68 88.46,46.31 98.52,36.25 98.52,34.3 TP221.1 96.44,32.22 U1712.18
ENET1_TD1: length 28.4
  TOP w0.081: U101.R9 88.74,49.45 88.74,48.3
  TOP w0.091: 88.74,48.3 88.74,46.34 98.74,36.34 98.74,33.9 96.79,31.94 91.89,31.94 91.77,31.82 U1712.17
ENET1_TD2: length 27.8
  TOP w0.091: U101.U10 88.99,46.4 98.96,36.43 98.96,33.77 96.91,31.72 92.63,31.72 92.32,31.42 U1712.16
ENET1_TD3: length 28.8
  TOP w0.081: U101.T10 89.24,48.95 89.24,48.21
  TOP w0.091: U1712.15 92.48,31.02 92.97,31.51 97,31.51 99.18,33.68 99.18,36.52 89.24,46.45 89.24,48.21
ENET1_TX_CTL: length 26.8
  TOP w0.081: 88.23,48.13 88.24,48.14 88.24,48.95 U101.T9
  TOP w0.091: 88.23,48.13 88.23,46.23 98.31,36.16 98.31,34.6 96.3,32.59 91.9,32.59 91.87,32.62 U1712.19
ENET1_TXC: length 27.3
  TOP w0.091: U101.U8 87.99,46.16 98.09,36.07 98.09,34.69 96.23,32.83 93.98,32.83 93.79,33.01 93.79,33.67 93.7,33.76 93.23,33.76 93.13,33.67 TP220.1 93.13,33.35 92.59,32.81 91.97,32.81 91.77,33.02 U1712.20
ETH1_10/100M_LINK/ACTIVE: length 22.6
  TOP w0.091: J501.13 89.88,4.78 79.61,15.05 79.61,20.65 80.26,21.3 R504.1
ETH1_1000M_LINK/ACTIVE: length 35.5
  TOP w0.091: J501.11 82.98,7.78 82.98,10.81 78.99,14.79 78.99,20.47 77.78,21.69 77.78,22 R507.1 78.16,22.08 78.33,22.25 78.33,23.2 79.03,23.9 79.03,33.27 80.3,34.54 R529.1
ETH1_AVDD1V0: length 24.1
  TOP w0.254: C517.1 85.36,30.22 U1712.38 ; U1712.3 v1(87.77,28.05) ; U1712.8 v1(89.77,28.05)
  TOP w0.381: v1(85.22,28.63) 85.12,28.63 84.79,28.3 C516.1
  TOP w0.508: v1(96.01,36.84) 96.32,36.53 R530.2 ; C516.1 C517.1
  BOTTOM w0.381: v1(89.77,28.05) 89.79,28.06 C515.1 ; C515.1 91.15,28.68 93.45,30.97 93.45,34.28 v1(96.01,36.84) ; C515.1 C518.1 ; v1(87.77,28.05) 87.78,28.06 C518.1 ; v1(85.22,28.63) 85.27,28.68 C518.1
ETH1_AVDD3V3: length 14.5
  TOP w0.254: 91.82,29.24 91.64,29.42 U1712.11 ; 86.31,29.11 U1712.40
  TOP w0.508: 91.82,29.24 92.68,28.38 92.68,28.15 C1743.1 93.14,26.67 L502.2 92.05,26.52 91.87,26.71 v1(91.62,26.71) ; 86.31,29.11 86.31,28.57 85.6,27.85 C1742.1 85.96,27.46 86.57,26.84 v1(86.57,26.63)
  BOTTOM w0.508: v1(86.57,26.63) 86.65,26.71 v1(91.62,26.71)
ETH1_CLK125_OUT: length 2.2
  TOP w0.091: TP1933.1 84.89,31.42 U1712.35
ETH1_CT: length 5
  TOP w0.091: C1738.1 82.55,20.85 80.9,19.2 J501.1
ETH1_DVDD1V0: length 5.9
  TOP w0.254: U1712.21 91.03,33.68
  TOP w0.508: 91.03,33.68 91.59,33.68 92.64,34.73 R531.2 93.45,34.73 94.02,35.3 C514.1 C513.1
ETH1_DVDD3V3: length 14.4
  TOP w0.254: U1712.29 87.37,35.58 C1739.1
  TOP w0.381: v1(81.65,35.01) 81.92,35.28 R512.1 ; v1(81.65,35.01) 81.41,34.77 81.41,33.48 82.4,32.49 R513.1 ; v1(81.65,35.01) 81.05,35.61 R529.2 ; v1(84.94,35.19) 84.71,35.42 L501.2 85.84,35.99 C1740.1 C1739.1
  BOTTOM w0.381: v1(81.65,35.01) 82.13,35.49 84.64,35.49 v1(84.94,35.19)
ETH1_LED0/CFG_EXT: length 18.7
  TOP w0.091: U1712.32 85.91,32.62 84.7,33.83 v1(84.66,33.83) 84.66,33.86 83.57,34.96 R512.2 R519.1 ; v1(80.58,28.09) 80.58,27.24 80.26,26.92 R504.2
  BOTTOM w0.091: v1(80.58,28.09) 81.26,28.76 81.26,30.32 82.95,32.01 82.95,33.14 83.92,34.11 84.57,34.11 84.66,34.02 v1(84.66,33.83)
ETH1_LED1/CFGLDO0: length 42.3
  TOP w0.091: J501.14 92.07,5.95 89.02,5.95 79.83,15.14 79.83,19.25 81.41,20.83 C520.1 81.12,22.08 80.86,22.34 80.86,27.76 v1(81.18,28.09) ; R521.1 83.6,34.26 v1(84.13,33.73) 85.65,32.22 U1712.33
  BOTTOM w0.091: v1(81.18,28.09) 81.47,28.38 81.47,29.86 83.27,31.66 83.27,32.81 84.13,33.67 v1(84.13,33.73)
ETH1_LED2/CFGLDO1: length 38.6
  TOP w0.091: v1(84.15,33.15) 83.92,33.38 R520.1 R513.2 84.67,32.49 85.34,31.82 U1712.34 ; J501.12 82.52,7 83.28,7.75 83.28,11.01 79.34,14.95 79.34,21.76 79.02,22.08 C521.1 78.68,22.08 78.57,22.19 78.57,23.13 80.02,24.58 v1(80.02,27.73)
  BOTTOM w0.091: v1(80.02,27.73) 80.04,27.71 81.51,27.71 82.09,28.29 82.09,30.17 84.15,32.22 v1(84.15,33.15)
ETH1_TRX0_N: length 17
  TOP w0.081: U1712.2 87.37,28.21 87.29,28.12 87.29,25.29 86.61,24.61 85.03,24.61 84.08,23.66 84.08,23.54 84.21,23.41 U503.9 U503.2 84.21,21.5 84.08,21.37 84.08,20.25 82.27,18.44 82.27,17.09 82.66,16.7 83.05,16.7 83.44,17.09 J501.3
ETH1_TRX0_P: length 17
  TOP w0.081: J501.2 82.52,15.56 82.52,16.51 82.04,16.99 82.04,18.54 83.84,20.34 83.84,21.37 83.71,21.5 U503.1 U503.10 83.71,23.41 83.84,23.54 83.84,23.75 84.93,24.84 86.51,24.84 87.06,25.39 87.06,28.12 86.97,28.21 U1712.1
ETH1_TRX1_N: length 16.2
  TOP w0.081: U1712.5 88.57,28.21 88.49,28.12 88.49,25.45 87.02,23.97 85.85,23.97 85.6,23.73 85.6,23.51 85.71,23.41 U503.6 U503.5 85.71,21.5 85.58,21.37 85.58,19.51 84.94,18.88 84.94,16.97 85.28,16.64 85.74,16.64 85.98,16.88 J501.5
ETH1_TRX1_P: length 16.3
  TOP w0.081: J501.4 85.21,15.72 85.21,16.37 84.71,16.88 84.71,18.97 85.34,19.61 85.34,21.37 85.21,21.5 U503.4 U503.7 85.21,23.41 85.37,23.57 85.37,23.83 85.75,24.21 86.92,24.21 88.26,25.54 88.26,28.12 88.17,28.21 U1712.4
ETH1_TRX2_N: length 14.9
  TOP w0.081: J501.7 88.52,17.01 88.15,16.64 87.81,16.64 87.36,17.1 87.36,18.55 88.52,19.71 88.52,21.37 88.65,21.5 U502.2 U502.9 88.65,23.41 88.52,23.54 88.52,23.66 89.18,24.32 89.18,27.56 89.29,27.67 89.29,28.12 89.37,28.21 U1712.7
ETH1_TRX2_P: length 14.9
  TOP w0.081: U1712.6 88.97,28.21 89.06,28.12 89.06,27.77 88.95,27.66 88.95,24.41 88.29,23.75 88.29,23.54 88.15,23.41 U502.10 U502.1 88.15,21.5 88.29,21.37 88.29,19.81 87.12,18.64 87.12,17 87.67,16.45 87.67,15.64 J501.6
ETH1_TRX3_N: length 14.7
  TOP w0.081: J501.9 91.06,16.77 90.98,16.69 90.29,16.69 89.92,17.06 89.92,20.14 90.02,20.25 90.02,21.37 90.15,21.5 U502.5 ; U1712.10 90.57,28.21 90.49,28.12 90.49,27.93 90.91,27.5 90.91,24.69 90.02,23.8 90.02,23.54 90.15,23.41 U502.6
  TOP w0.091: U502.5 U502.6
ETH1_TRX3_P: length 14.8
  TOP w0.081: U502.4 89.65,21.5 89.79,21.37 89.79,20.35 89.68,20.24 89.68,16.96 90.34,16.31 90.34,15.77 J501.8 ; U1712.9 90.17,28.21 90.26,28.12 90.26,27.83 90.68,27.41 90.68,24.79 89.79,23.9 89.79,23.54 89.65,23.41 U502.7
  TOP w0.091: U502.7 U502.4
ETH1_VDD1V0: length 26.9
  TOP w0.254: v1(86.8,34.39) 86.97,34.22 U1712.30
  TOP w0.508: R530.1 95.5,34.71 v1(95.46,34.76) 95.43,34.73 R531.1
  BOTTOM w0.381: C511.1 87.12,34.07 v1(86.8,34.39) 86.23,34.39 C512.1 85.58,34.01 84.67,33.1 84.67,28.45 85.76,27.36 90.89,27.36 94.01,30.48 94.01,34.11 94.65,34.76 v1(95.46,34.76)
ETH1_VDDIO: length 26.7
  TOP w0.254: U1712.28 87.77,34.34 v1(87.87,34.44)
  TOP w0.381: R516.1 87.88,40.56 v1(87.93,40.61) ; R514.1 v1(91.95,40.4) ; v1(93.69,39.19) 93.16,39.73 R515.1 ; R517.1 v1(89.92,40.47) ; R510.2 v1(80.64,33.74) ; R518.1 v1(90.93,40.43)
  BOTTOM w0.381: C1745.1 88.9,33.76 C1746.1 88.01,34.3 v1(87.87,34.44) 88.46,35.03 88.46,38.01 87.72,38.75 87.72,40.4 v1(87.93,40.61) 89.78,40.61 v1(89.92,40.47) 90.88,40.47 v1(90.93,40.43) 91.92,40.43 v1(91.95,40.4) 92.48,40.4 v1(93.69,39.19) ; v1(80.64,33.74) 80.77,33.61 82.29,33.61 83.27,34.6 85.09,34.6 85.63,35.15 86.1,35.15
ETH1_XTALI: length 8
  TOP w0.091: U1712.36 84.52,31.02 R511.2 84.16,30.96 83.64,31.47 C510.1 83.29,31.46 83.29,31.06 83.2,30.97 81.95,30.97 81.64,30.66 80.05,30.66 79.74,30.97 Y501.3
ETH1_XTALO: length 6.3
  TOP w0.091: Y501.1 81.29,29.68 81.92,30.31 81.92,30.61 82.07,30.75 83.21,30.75 83.31,30.66 C1741.1 84.33,30.33 R511.1 84.85,30.21 85.26,30.62 U1712.37
EXP3V3_EN: length 15.3
  TOP w0.091: v1(107.61,71.7) 107.7,71.78 v1(107.7,73.64) ; R858.2 107.99,67.8 107.5,68.29 v1(107.35,68.29)
  BOTTOM w0.091: R1825.1 101.64,76.44 104.15,73.93 104.64,73.93 104.93,73.64 v1(107.7,73.64) ; v1(107.61,71.7) 107.61,71.55 107.35,71.28 v1(107.35,68.29)
EXP5V_EN: length 52
  TOP w0.091: R806.2 v1(107.66,57.13)
  BOTTOM w0.091: R16.1 75.59,72.17 76.16,71.59 80.98,71.59 81.5,72.11 84.93,72.11 85.44,71.59 87.12,71.59 90.46,74.94 101.9,74.94 104.3,72.54 105.57,72.54 106.59,71.51 106.59,67.65 107.82,66.42 107.82,57.29 v1(107.66,57.13)
EXP_3V3: length 18.4
  BOTTOM w0.381: C1405.1 94.22,77.43 94.84,76.81 U1714.5 U1714.1
  BOTTOM w0.508: C1405.1 92.49,78.41 90.56,80.34 87.73,80.34 84.76,77.37 v1(83.83,77.37)
EXP_5V:
  vias: v1(82.68,80.41) v1(83.02,81.02)
EXP_GPIO_IO08: length 12.5
  TOP w0.102: J1401.24 116.13,80.02 114.73,78.62 114.73,74.13 114.09,73.49 112.45,73.49 111.44,72.48 U805.1
EXP_GPIO_IO09: length 6.8
  TOP w0.102: J1401.21 113.59,75.14 112.39,73.94 110.89,73.94 110.24,73.29 U805.4
EXP_GPIO_IO10: length 8.1
  TOP w0.102: J1401.19 111.05,75.15 108.43,72.54 108.43,70.61 108.64,70.41 U805.8
EXP_GPIO_IO11: length 12.4
  TOP w0.102: J1401.23 116.13,74.22 115.57,73.66 115.57,69.96 114.71,69.1 111.55,69.1 111.04,69.61 U805.11
EXP_GPIO_IO12: length 98.5
  TOP w0.091: R1438.1 71.95,83.99 v1(71.87,83.91)
  TOP w0.102: U803.1 132.57,70.7 v1(132.63,70.64) 133.09,70.64 133.37,70.37 133.37,67.33 131.97,65.93 128.85,65.93 128.23,66.56 128.23,70.3 128.73,70.8 128.73,73.22 127.44,74.52 127.44,78.26 126.29,79.41 J1401.32
  BOTTOM w0.091: v1(71.87,83.91) 125.96,83.91 133.12,76.76 133.12,71.14 v1(132.63,70.64)
EXP_GPIO_IO16: length 46.6
  TOP w0.091: U804.1 101.49,72.72 101.99,73.23 101.99,78.44 101.45,78.98 100.13,78.98 99.74,79.37 99.74,83.19 101.36,84.8
  TOP w0.102: v1(129.94,84.57) 129.7,84.8 101.36,84.8
  BOTTOM w0.091: R1829.1 130.53,83.12 R856.2 130.53,83.98 v1(129.94,84.57)
EXP_GPIO_IO17: length 4.3
  TOP w0.091: J1401.11 100.89,74.51 100.29,73.91 U804.4
EXP_GPIO_IO18: length 16.2
  TOP w0.091: v1(132.47,74.29) 132.47,77.86 133.18,78.58 v1(133.18,78.93) ; U803.4 132.51,71.9 v1(132.74,72.13)
  BOTTOM w0.091: v1(133.18,78.93) 131.27,80.84 131.28,80.85 R1829.2 ; R855.2 132.47,75.05 v1(132.47,74.29) 132.47,72.41 v1(132.74,72.13)
EXP_GPIO_IO19: length 9.5
  TOP w0.091: R745.2 127.33,70.48 v1(127.41,70.4) ; U803.8 130.25,72.51 129.89,72.87 v1(129.81,72.87)
  TOP w0.102: U803.8 130.62,73.74 131.37,74.49 J1401.35
  L3_PWR w0.114: v1(129.81,72.87) 129.44,72.87 127.41,70.83 v1(127.41,70.4)
EXP_GPIO_IO20: length 14
  TOP w0.102: U803.11 129.76,71.1 129.43,71.43 129.43,73.24 130.35,74.16 130.35,78.46 130.6,78.71 132.43,78.71 133.91,80.19 J1401.38
EXP_GPIO_IO21: length 54.7
  TOP w0.102: J1401.40 136.45,83.62 135.04,85.03 101.19,85.03 99.52,83.36 99.52,73.43 98.34,72.26 98.34,71.03 98.44,70.93 U804.8
EXP_NIRQ: length 96.4
  TOP w0.081: U101.T4 85.74,48.95 85.74,48.35 85.74,48.35
  TOP w0.091: R813.1 v1(103.54,56.94) ; 85.74,47.45 85.74,48.35
  TOP w0.102: 85.74,47.45 84.74,46.44 84.74,42.58 78.64,36.48 78.64,34.48 77.9,33.74 77.9,25.29 76.4,23.8 v1(76.4,23.08)
  BOTTOM w0.091: v1(103.54,56.94) 103.54,56.02 112.46,47.1 112.46,36.67 109.73,33.94 103.47,33.94 102.84,33.31 101.88,33.31 91.47,22.89 76.59,22.89 v1(76.4,23.08)
EXP_SEL: length 81
  TOP w0.091: v1(113.43,68.24) 113,68.66 108.57,68.66 108.07,69.16 v1(106.97,69.16) ; U804.15 106.46,71.73 106.65,71.92 v1(106.73,71.92) 106.84,71.92 107.06,72.14 107.06,83.47 107.72,84.13 126.55,84.13 127.44,83.24 127.44,78.79 127.85,78.38 127.85,74.42 128.96,73.31 128.96,70.71 128.45,70.21 128.45,66.65 128.94,66.16 131.88,66.16 133.12,67.4 133.12,68.15 132.9,68.37 R838.1 132.61,68.55 131.42,69.75 U803.15 ; v1(112.91,71.97) 112.91,71.58 112.53,71.21 U805.15 ; R836.2 v1(106.97,67.81)
  BOTTOM w0.091: v1(112.91,71.97) 113.43,71.45 v1(113.43,68.24) ; v1(106.97,67.81) 106.81,67.96 106.81,69 v1(106.97,69.16) 106.97,71.69 v1(106.73,71.92)
EXT1_PWREN: length 41.2
  TOP w0.091: R825.2 v1(115.76,63.22) ; R922.1 127.81,33.56 127.72,33.56 125.74,35.55 122.35,35.55 120.08,37.82 v1(118.25,37.82)
  BOTTOM w0.091: v1(118.25,37.82) 117.85,38.22 117.85,41.66 116.46,43.05 116.46,48.42 113.3,51.58 113.3,57.5 115.17,59.37 115.17,62.15 115.76,62.75 v1(115.76,63.22)
